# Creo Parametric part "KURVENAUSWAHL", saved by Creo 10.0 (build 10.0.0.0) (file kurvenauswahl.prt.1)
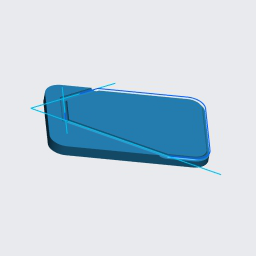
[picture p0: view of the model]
Materials in the file: S235JRG2

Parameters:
  BENENNUNG = "XXX"
  DATUM = "XX.XX.XX"
  ERSTELLER = "ARINDA"
  TEILETYP = "Fertigungsteil"
  PTC_MASTER_MATERIAL = "S235JRG2"
  SELECT_EN_NAME = "S235JRG2"
  SELECT_DIN_NAME = "RSt37-2"
  SELECT_DIN_NUMBER = "1.0038"
  SELECT_ASTM_NAME = "A 283 M Grade 2"
  MATERIAL_GROUP = "ME_ST_Baustahl"
  STANDARD_EN_DELIVERYSPEC = "DIN EN 10025"
  STANDARD_DIN_DELIVERYSPEC = "DIN 17100"

Other parameters: MASSE

Created from: ARINDA-STARTTEIL.PRT

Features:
  1. coordinate system
  2. datum plane "T_RECHTS_Y-Z"
  3. datum plane "T_OBEN_X-Z"
  4. datum plane "T_VORNE_X-Y"
  5. datum axis
  6. datum axis
  7. datum axis
  8. extrusion "Profil 1"
  9. round "Rundung 1"
  10. sketch "Skizze 1"
  11. datum plane "DTM1"
  12. curve "Kurve 1"
  13. swept cut "Ziehen 1"
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
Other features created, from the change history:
  sketch "Skizze 2"
  curve "Kurve 2"
  extrusion "Profil 2"
  datum plane "DTM1"
  sketch "Skizze 3"

Other named items: T_BASIC, T_X-ACHSE, T_Y-ACHSE, T_Z-ACHSE

Layers: 00_STD-ACHSEN, 00_STD-EBENEN, 00_STD-KOORDSYS, 01_EBENEN, 01_KURVEN, KURVENELEMENTE, VOLUMENGEOMETRIE

Surfaces: 10 cylinder, 6 plane, 2 torus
